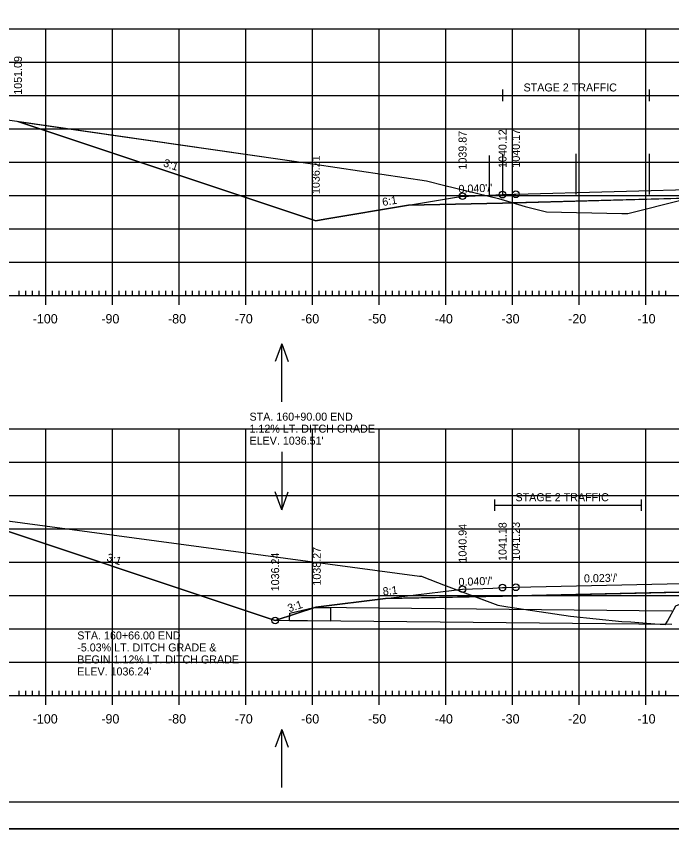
# Model space of a CAD drawing. Extents: x 1322838 to 1324533, y 339903 to 351025.
# Drawn here: x 1323599.3 to 1323697.6, y 345752.1 to 345873.9 of the extents above; entities that cross this region are included whole.
import ezdxf

# ---------------------------------------------------------------- set-up
doc = ezdxf.new("R2010")
doc.units = 0
for name, color, linetype in [('1', 7, 'Continuous'), ('R_Alt Surface', 7, 'Continuous'), ('R_Axis', 7, 'Continuous'), ('R_Axis Annot', 7, 'Continuous'), ('R_Border', 7, 'Continuous'), ('R_Drive', 7, 'Continuous'), ('R_Exist Surface', 7, 'Continuous'), ('R_Fin Surface', 7, 'Continuous'), ('R_Fin Surface Annot', 7, 'Continuous'), ('R_Grid', 7, 'Continuous'), ('R_No Plot', 7, 'Continuous'), ('R_Water', 7, 'Continuous'), ('R_Water Annot', 7, 'Continuous')]:
    doc.layers.add(name, color=color, linetype=linetype)

msp = doc.modelspace()

# ---------------------------------------------------------------- linework, layer by layer
at = {"layer": '1'}
msp.add_lwpolyline([(1323646.43, 345785.23), (1323646.41, 345783.23), (1323640.29, 345783.3), (1323640.3, 345784.42), (1323643.93, 345785.26)], close=True, dxfattribs=at)
at = {"layer": 'R_Alt Surface'}
for points in [[(1323658.11, 345845.61), (1323672.22, 345845.91), (1323710.1, 345846.95), (1323710.11, 345848.08), (1323732.11, 345848.69), (1323732.12, 345847.56), (1323735.22, 345847.65), (1323748.08, 345847.39)], [(1323654.65, 345786.62), (1323672.22, 345786.97), (1323710.03, 345787.84), (1323710.04, 345788.97), (1323732.03, 345789.47), (1323732.04, 345788.35), (1323735.22, 345788.42), (1323747.96, 345788.16)]]:
    msp.add_lwpolyline(points, dxfattribs=at)
at = {"layer": 'R_Axis'}
for p, q in [((1323599.72, 345832.08), (1323599.72, 345832.78)), ((1323600.72, 345832.08), (1323600.72, 345832.78)), ((1323601.72, 345832.08), (1323601.72, 345832.78)), ((1323602.72, 345832.08), (1323602.72, 345832.78)), ((1323603.72, 345830.68), (1323603.72, 345833.48)), ((1323604.72, 345832.08), (1323604.72, 345832.78)), ((1323605.72, 345832.08), (1323605.72, 345832.78)), ((1323606.72, 345832.08), (1323606.72, 345832.78)), ((1323607.72, 345832.08), (1323607.72, 345832.78)), ((1323608.72, 345832.08), (1323608.72, 345832.78)), ((1323609.72, 345832.08), (1323609.72, 345832.78)), ((1323610.72, 345832.08), (1323610.72, 345832.78)), ((1323611.72, 345832.08), (1323611.72, 345832.78)), ((1323612.72, 345832.08), (1323612.72, 345832.78)), ((1323613.72, 345830.68), (1323613.72, 345833.48)), ((1323614.72, 345832.08), (1323614.72, 345832.78)), ((1323615.72, 345832.08), (1323615.72, 345832.78)), ((1323616.72, 345832.08), (1323616.72, 345832.78)), ((1323617.72, 345832.08), (1323617.72, 345832.78)), ((1323618.72, 345832.08), (1323618.72, 345832.78)), ((1323619.72, 345832.08), (1323619.72, 345832.78)), ((1323620.72, 345832.08), (1323620.72, 345832.78)), ((1323621.72, 345832.08), (1323621.72, 345832.78)), ((1323622.72, 345832.08), (1323622.72, 345832.78)), ((1323623.72, 345830.68), (1323623.72, 345833.48)), ((1323624.72, 345832.08), (1323624.72, 345832.78)), ((1323625.72, 345832.08), (1323625.72, 345832.78)), ((1323626.72, 345832.08), (1323626.72, 345832.78)), ((1323627.72, 345832.08), (1323627.72, 345832.78)), ((1323628.72, 345832.08), (1323628.72, 345832.78)), ((1323629.72, 345832.08), (1323629.72, 345832.78)), ((1323630.72, 345832.08), (1323630.72, 345832.78)), ((1323631.72, 345832.08), (1323631.72, 345832.78)), ((1323632.72, 345832.08), (1323632.72, 345832.78)), ((1323633.72, 345830.68), (1323633.72, 345833.48)), ((1323634.72, 345832.08), (1323634.72, 345832.78)), ((1323635.72, 345832.08), (1323635.72, 345832.78)), ((1323636.72, 345832.08), (1323636.72, 345832.78)), ((1323637.72, 345832.08), (1323637.72, 345832.78)), ((1323638.72, 345832.08), (1323638.72, 345832.78)), ((1323639.72, 345832.08), (1323639.72, 345832.78)), ((1323640.72, 345832.08), (1323640.72, 345832.78)), ((1323641.72, 345832.08), (1323641.72, 345832.78)), ((1323642.72, 345832.08), (1323642.72, 345832.78)), ((1323643.72, 345830.68), (1323643.72, 345833.48)), ((1323644.72, 345832.08), (1323644.72, 345832.78)), ((1323645.72, 345832.08), (1323645.72, 345832.78)), ((1323646.72, 345832.08), (1323646.72, 345832.78)), ((1323647.72, 345832.08), (1323647.72, 345832.78)), ((1323648.72, 345832.08), (1323648.72, 345832.78)), ((1323649.72, 345832.08), (1323649.72, 345832.78)), ((1323650.72, 345832.08), (1323650.72, 345832.78)), ((1323651.72, 345832.08), (1323651.72, 345832.78)), ((1323652.72, 345832.08), (1323652.72, 345832.78)), ((1323653.72, 345830.68), (1323653.72, 345833.48)), ((1323654.72, 345832.08), (1323654.72, 345832.78)), ((1323655.72, 345832.08), (1323655.72, 345832.78)), ((1323656.72, 345832.08), (1323656.72, 345832.78)), ((1323657.72, 345832.08), (1323657.72, 345832.78)), ((1323658.72, 345832.08), (1323658.72, 345832.78)), ((1323659.72, 345832.08), (1323659.72, 345832.78)), ((1323660.72, 345832.08), (1323660.72, 345832.78)), ((1323661.72, 345832.08), (1323661.72, 345832.78)), ((1323662.72, 345832.08), (1323662.72, 345832.78)), ((1323663.72, 345830.68), (1323663.72, 345833.48)), ((1323664.72, 345832.08), (1323664.72, 345832.78)), ((1323665.72, 345832.08), (1323665.72, 345832.78)), ((1323666.72, 345832.08), (1323666.72, 345832.78)), ((1323667.72, 345832.08), (1323667.72, 345832.78)), ((1323668.72, 345832.08), (1323668.72, 345832.78)), ((1323669.72, 345832.08), (1323669.72, 345832.78)), ((1323670.72, 345832.08), (1323670.72, 345832.78)), ((1323671.72, 345832.08), (1323671.72, 345832.78)), ((1323672.72, 345832.08), (1323672.72, 345832.78)), ((1323673.72, 345830.68), (1323673.72, 345833.48)), ((1323674.72, 345832.08), (1323674.72, 345832.78)), ((1323675.72, 345832.08), (1323675.72, 345832.78)), ((1323676.72, 345832.08), (1323676.72, 345832.78)), ((1323677.72, 345832.08), (1323677.72, 345832.78)), ((1323678.72, 345832.08), (1323678.72, 345832.78)), ((1323679.72, 345832.08), (1323679.72, 345832.78)), ((1323680.72, 345832.08), (1323680.72, 345832.78)), ((1323681.72, 345832.08), (1323681.72, 345832.78)), ((1323682.72, 345832.08), (1323682.72, 345832.78)), ((1323683.72, 345830.68), (1323683.72, 345833.48)), ((1323684.72, 345832.08), (1323684.72, 345832.78)), ((1323685.72, 345832.08), (1323685.72, 345832.78)), ((1323686.72, 345832.08), (1323686.72, 345832.78)), ((1323687.72, 345832.08), (1323687.72, 345832.78)), ((1323688.72, 345832.08), (1323688.72, 345832.78)), ((1323689.72, 345832.08), (1323689.72, 345832.78)), ((1323690.72, 345832.08), (1323690.72, 345832.78)), ((1323691.72, 345832.08), (1323691.72, 345832.78)), ((1323692.72, 345832.08), (1323692.72, 345832.78)), ((1323693.72, 345830.68), (1323693.72, 345833.48)), ((1323694.72, 345832.08), (1323694.72, 345832.78)), ((1323695.72, 345832.08), (1323695.72, 345832.78)), ((1323696.72, 345832.08), (1323696.72, 345832.78)), ((1323563.72, 345832.08), (1323843.72, 345832.08)), ((1323599.72, 345772.08), (1323599.72, 345772.78)), ((1323600.72, 345772.08), (1323600.72, 345772.78)), ((1323601.72, 345772.08), (1323601.72, 345772.78)), ((1323602.72, 345772.08), (1323602.72, 345772.78)), ((1323603.72, 345770.68), (1323603.72, 345773.48)), ((1323604.72, 345772.08), (1323604.72, 345772.78)), ((1323605.72, 345772.08), (1323605.72, 345772.78)), ((1323606.72, 345772.08), (1323606.72, 345772.78)), ((1323607.72, 345772.08), (1323607.72, 345772.78)), ((1323608.72, 345772.08), (1323608.72, 345772.78)), ((1323609.72, 345772.08), (1323609.72, 345772.78)), ((1323610.72, 345772.08), (1323610.72, 345772.78)), ((1323611.72, 345772.08), (1323611.72, 345772.78)), ((1323612.72, 345772.08), (1323612.72, 345772.78)), ((1323613.72, 345770.68), (1323613.72, 345773.48)), ((1323614.72, 345772.08), (1323614.72, 345772.78)), ((1323615.72, 345772.08), (1323615.72, 345772.78)), ((1323616.72, 345772.08), (1323616.72, 345772.78)), ((1323617.72, 345772.08), (1323617.72, 345772.78)), ((1323618.72, 345772.08), (1323618.72, 345772.78)), ((1323619.72, 345772.08), (1323619.72, 345772.78)), ((1323620.72, 345772.08), (1323620.72, 345772.78)), ((1323621.72, 345772.08), (1323621.72, 345772.78)), ((1323622.72, 345772.08), (1323622.72, 345772.78)), ((1323623.72, 345770.68), (1323623.72, 345773.48)), ((1323624.72, 345772.08), (1323624.72, 345772.78)), ((1323625.72, 345772.08), (1323625.72, 345772.78)), ((1323626.72, 345772.08), (1323626.72, 345772.78)), ((1323627.72, 345772.08), (1323627.72, 345772.78)), ((1323628.72, 345772.08), (1323628.72, 345772.78)), ((1323629.72, 345772.08), (1323629.72, 345772.78)), ((1323630.72, 345772.08), (1323630.72, 345772.78)), ((1323631.72, 345772.08), (1323631.72, 345772.78)), ((1323632.72, 345772.08), (1323632.72, 345772.78)), ((1323633.72, 345770.68), (1323633.72, 345773.48)), ((1323634.72, 345772.08), (1323634.72, 345772.78)), ((1323635.72, 345772.08), (1323635.72, 345772.78)), ((1323636.72, 345772.08), (1323636.72, 345772.78)), ((1323637.72, 345772.08), (1323637.72, 345772.78)), ((1323638.72, 345772.08), (1323638.72, 345772.78)), ((1323639.72, 345772.08), (1323639.72, 345772.78)), ((1323640.72, 345772.08), (1323640.72, 345772.78)), ((1323641.72, 345772.08), (1323641.72, 345772.78)), ((1323642.72, 345772.08), (1323642.72, 345772.78)), ((1323643.72, 345770.68), (1323643.72, 345773.48)), ((1323644.72, 345772.08), (1323644.72, 345772.78)), ((1323645.72, 345772.08), (1323645.72, 345772.78)), ((1323646.72, 345772.08), (1323646.72, 345772.78)), ((1323647.72, 345772.08), (1323647.72, 345772.78)), ((1323648.72, 345772.08), (1323648.72, 345772.78)), ((1323649.72, 345772.08), (1323649.72, 345772.78)), ((1323650.72, 345772.08), (1323650.72, 345772.78)), ((1323651.72, 345772.08), (1323651.72, 345772.78)), ((1323652.72, 345772.08), (1323652.72, 345772.78)), ((1323653.72, 345770.68), (1323653.72, 345773.48)), ((1323654.72, 345772.08), (1323654.72, 345772.78)), ((1323655.72, 345772.08), (1323655.72, 345772.78)), ((1323656.72, 345772.08), (1323656.72, 345772.78)), ((1323657.72, 345772.08), (1323657.72, 345772.78)), ((1323658.72, 345772.08), (1323658.72, 345772.78)), ((1323659.72, 345772.08), (1323659.72, 345772.78)), ((1323660.72, 345772.08), (1323660.72, 345772.78)), ((1323661.72, 345772.08), (1323661.72, 345772.78)), ((1323662.72, 345772.08), (1323662.72, 345772.78)), ((1323663.72, 345770.68), (1323663.72, 345773.48)), ((1323664.72, 345772.08), (1323664.72, 345772.78)), ((1323665.72, 345772.08), (1323665.72, 345772.78)), ((1323666.72, 345772.08), (1323666.72, 345772.78)), ((1323667.72, 345772.08), (1323667.72, 345772.78)), ((1323668.72, 345772.08), (1323668.72, 345772.78)), ((1323669.72, 345772.08), (1323669.72, 345772.78)), ((1323670.72, 345772.08), (1323670.72, 345772.78)), ((1323671.72, 345772.08), (1323671.72, 345772.78)), ((1323672.72, 345772.08), (1323672.72, 345772.78)), ((1323673.72, 345770.68), (1323673.72, 345773.48)), ((1323674.72, 345772.08), (1323674.72, 345772.78)), ((1323675.72, 345772.08), (1323675.72, 345772.78)), ((1323676.72, 345772.08), (1323676.72, 345772.78)), ((1323677.72, 345772.08), (1323677.72, 345772.78)), ((1323678.72, 345772.08), (1323678.72, 345772.78)), ((1323679.72, 345772.08), (1323679.72, 345772.78)), ((1323680.72, 345772.08), (1323680.72, 345772.78)), ((1323681.72, 345772.08), (1323681.72, 345772.78)), ((1323682.72, 345772.08), (1323682.72, 345772.78)), ((1323683.72, 345770.68), (1323683.72, 345773.48)), ((1323684.72, 345772.08), (1323684.72, 345772.78)), ((1323685.72, 345772.08), (1323685.72, 345772.78)), ((1323686.72, 345772.08), (1323686.72, 345772.78)), ((1323687.72, 345772.08), (1323687.72, 345772.78)), ((1323688.72, 345772.08), (1323688.72, 345772.78)), ((1323689.72, 345772.08), (1323689.72, 345772.78)), ((1323690.72, 345772.08), (1323690.72, 345772.78)), ((1323691.72, 345772.08), (1323691.72, 345772.78)), ((1323692.72, 345772.08), (1323692.72, 345772.78)), ((1323693.72, 345770.68), (1323693.72, 345773.48)), ((1323694.72, 345772.08), (1323694.72, 345772.78)), ((1323695.72, 345772.08), (1323695.72, 345772.78)), ((1323696.72, 345772.08), (1323696.72, 345772.78)), ((1323563.72, 345772.08), (1323843.72, 345772.08))]:
    msp.add_line(p, q, dxfattribs=at)
at = {"layer": 'R_Axis Annot'}
for p, q in [((1323672.22, 345862.94), (1323672.22, 345861.23)), ((1323694.22, 345862.94), (1323694.22, 345861.23)), ((1323672.22, 345862.08), (1323694.22, 345862.08)), ((1323671.01, 345801.49), (1323671.01, 345799.78)), ((1323693.01, 345801.49), (1323693.01, 345799.78)), ((1323671.01, 345800.63), (1323693.01, 345800.63))]:
    msp.add_line(p, q, dxfattribs=at)
at = {"layer": 'R_Border'}
msp.add_line((1323861.9, 345756.08), (1323545.72, 345756.08), dxfattribs=at)
at = {"layer": 'R_Exist Surface'}
for points in [[(1323563.72, 345863.82), (1323572.81, 345862.34), (1323594.51, 345858.91), (1323644.06, 345851.75), (1323660.82, 345849.29), (1323663.56, 345848.56), (1323671.61, 345846.6), (1323675.63, 345845.41), (1323678.82, 345844.61), (1323690.12, 345844.38), (1323691.01, 345844.36), (1323691.58, 345844.51), (1323698.53, 345846.25)], [(1323563.72, 345803.99), (1323566.4, 345803.53), (1323588.01, 345799.93), (1323596.88, 345798.45), (1323659.75, 345790), (1323660.09, 345789.97), (1323660.43, 345789.83), (1323663.37, 345788.7), (1323671.5, 345785.64), (1323673.03, 345785.38), (1323682.43, 345783.99), (1323690.08, 345783.19), (1323691.46, 345783.11), (1323695.07, 345782.85), (1323696.66, 345782.74), (1323696.96, 345783.21), (1323698.22, 345785.54)]]:
    msp.add_lwpolyline(points, dxfattribs=at)
at = {"layer": 'R_Fin Surface'}
for points in [[(1323599.56, 345858.18), (1323644.21, 345843.29), (1323644.21, 345843.29), (1323645.56, 345843.52), (1323658.11, 345845.61), (1323666.22, 345846.96), (1323667.13, 345846.99), (1323672.22, 345847.2), (1323673.97, 345847.25), (1323674.22, 345847.25), (1323703.71, 345848.07), (1323703.72, 345848.07), (1323703.72, 345848.07), (1323733.22, 345848.88), (1323734.69, 345848.93), (1323735.22, 345848.94), (1323736.85, 345848.99), (1323741.22, 345849.11), (1323746.33, 345847.83), (1323748.08, 345847.39), (1323748.08, 345847.39), (1323763.22, 345843.61), (1323767.9, 345842.04), (1323768.87, 345841.72)], [(1323588.62, 345799.82), (1323588.8, 345799.8), (1323638.12, 345783.32), (1323638.12, 345783.32), (1323644.21, 345785.35), (1323644.22, 345785.35), (1323644.22, 345785.35), (1323654.65, 345786.62), (1323666.22, 345788.02), (1323666.22, 345788.02), (1323670.77, 345788.2), (1323672.21, 345788.26), (1323672.22, 345788.26), (1323672.68, 345788.27), (1323674.22, 345788.31), (1323703.7, 345788.99)]]:
    msp.add_lwpolyline(points, dxfattribs=at)
at = {"layer": 'R_Grid'}
for p, q in [((1323563.72, 345872.08), (1323843.72, 345872.08)), ((1323603.72, 345832.08), (1323603.72, 345872.08)), ((1323613.72, 345832.08), (1323613.72, 345872.08)), ((1323623.72, 345832.08), (1323623.72, 345872.08)), ((1323633.72, 345832.08), (1323633.72, 345872.08)), ((1323643.72, 345832.08), (1323643.72, 345872.08)), ((1323653.72, 345832.08), (1323653.72, 345872.08)), ((1323663.72, 345832.08), (1323663.72, 345872.08)), ((1323673.72, 345832.08), (1323673.72, 345872.08)), ((1323683.72, 345832.08), (1323683.72, 345872.08)), ((1323693.72, 345832.08), (1323693.72, 345872.08)), ((1323563.72, 345867.08), (1323843.72, 345867.08)), ((1323563.72, 345862.08), (1323843.72, 345862.08)), ((1323563.72, 345857.08), (1323843.72, 345857.08)), ((1323563.72, 345852.08), (1323843.72, 345852.08)), ((1323563.72, 345847.08), (1323843.72, 345847.08)), ((1323563.72, 345842.08), (1323843.72, 345842.08)), ((1323563.72, 345837.08), (1323843.72, 345837.08)), ((1323563.72, 345832.08), (1323843.72, 345832.08)), ((1323563.72, 345812.08), (1323843.72, 345812.08)), ((1323603.72, 345772.08), (1323603.72, 345812.08)), ((1323613.72, 345772.08), (1323613.72, 345812.08)), ((1323623.72, 345772.08), (1323623.72, 345812.08)), ((1323633.72, 345772.08), (1323633.72, 345812.08)), ((1323643.72, 345772.08), (1323643.72, 345812.08)), ((1323653.72, 345772.08), (1323653.72, 345812.08)), ((1323663.72, 345772.08), (1323663.72, 345812.08)), ((1323673.72, 345772.08), (1323673.72, 345812.08)), ((1323683.72, 345772.08), (1323683.72, 345812.08)), ((1323693.72, 345772.08), (1323693.72, 345812.08)), ((1323563.72, 345807.08), (1323843.72, 345807.08)), ((1323563.72, 345802.08), (1323843.72, 345802.08)), ((1323563.72, 345797.08), (1323843.72, 345797.08)), ((1323563.72, 345792.08), (1323843.72, 345792.08)), ((1323563.72, 345787.08), (1323843.72, 345787.08)), ((1323563.72, 345782.08), (1323843.72, 345782.08)), ((1323563.72, 345777.08), (1323843.72, 345777.08)), ((1323563.72, 345772.08), (1323843.72, 345772.08))]:
    msp.add_line(p, q, dxfattribs=at)
at = {"layer": 'R_No Plot'}
for p, q in [((1323670.22, 345853.08), (1323670.22, 345846.97)), ((1323672.22, 345853.34), (1323672.22, 345847.23)), ((1323683.22, 345853.34), (1323683.22, 345847.23)), ((1323694.22, 345853.34), (1323694.22, 345847.23)), ((1323533.31, 345752.1), (1323866.65, 345752.1))]:
    msp.add_line(p, q, dxfattribs=at)
for points in [[(1323533.31, 345965.44), (1323866.65, 345965.44), (1323866.65, 345752.1), (1323533.31, 345752.1)], [(1323779.64, 345961.54), (1323799.26, 345961.54), (1323799.26, 345951.66), (1323815.37, 345951.66), (1323838.57, 345951.66), (1323838.57, 345918.99), (1323861.77, 345918.99), (1323861.9, 345756.08), (1323545.72, 345756.08), (1323545.72, 345961.54)], [(1323599.56, 345858.18), (1323644.06, 345851.75), (1323660.82, 345849.29), (1323663.56, 345848.56), (1323671.61, 345846.6), (1323673.81, 345845.95), (1323672.22, 345845.91), (1323658.11, 345845.61), (1323645.56, 345843.52), (1323644.21, 345843.29), (1323644.21, 345843.29)], [(1323673.81, 345845.95), (1323675.63, 345845.41), (1323678.82, 345844.61), (1323690.12, 345844.38), (1323691.01, 345844.36), (1323691.58, 345844.51), (1323698.53, 345846.25), (1323702.07, 345846.73)], [(1323588.8, 345799.79), (1323596.88, 345798.45), (1323659.75, 345790), (1323660.09, 345789.97), (1323660.43, 345789.83), (1323663.37, 345788.7), (1323668.18, 345786.89), (1323654.65, 345786.62), (1323644.22, 345785.35), (1323644.22, 345785.35), (1323644.21, 345785.35), (1323638.12, 345783.32), (1323638.12, 345783.32)], [(1323668.18, 345786.89), (1323671.5, 345785.64), (1323673.03, 345785.38), (1323682.43, 345783.99), (1323690.08, 345783.19), (1323691.46, 345783.11), (1323695.07, 345782.85), (1323696.66, 345782.74), (1323696.96, 345783.21), (1323698.22, 345785.54), (1323700.51, 345786.48), (1323700.71, 345786.6), (1323704.78, 345787.69), (1323704.8, 345787.7), (1323704.8, 345787.7), (1323705.25, 345787.73), (1323672.22, 345786.97)]]:
    msp.add_lwpolyline(points, close=True, dxfattribs=at)
for centre in [(1323666.22, 345846.96), (1323672.22, 345847.2), (1323674.22, 345847.25), (1323666.22, 345788.02), (1323672.22, 345788.26), (1323674.22, 345788.31), (1323638.12, 345783.32)]:
    msp.add_circle(centre, 0.5, dxfattribs=at)
at = {"layer": 'R_Water'}
for p, q in [((1323697.59, 345784.72), (1323643.93, 345785.26)), ((1323697.59, 345782.72), (1323638.05, 345783.32))]:
    msp.add_line(p, q, dxfattribs=at)
at = {"layer": 'R_Water Annot'}
for p, q in [((1323639.11, 345824.83), (1323638.14, 345822.17)), ((1323639.11, 345816.14), (1323639.11, 345824.83)), ((1323639.11, 345824.83), (1323640.08, 345822.17)), ((1323639.11, 345808.64), (1323639.11, 345799.95)), ((1323639.11, 345799.95), (1323638.14, 345802.61)), ((1323639.11, 345799.95), (1323640.08, 345802.61)), ((1323639.11, 345766.97), (1323638.14, 345764.31)), ((1323639.11, 345758.28), (1323639.11, 345766.97)), ((1323639.11, 345766.97), (1323640.08, 345764.31))]:
    msp.add_line(p, q, dxfattribs=at)

# ---------------------------------------------------------------- texts
at = {"layer": 'R_Axis Annot'}
for s, height, p in [('STAGE 2 TRAFFIC', 1.2, (1323675.37, 345862.67)), ('-100', 1.4, (1323601.77, 345827.88)), ('-90', 1.4, (1323612.06, 345827.88)), ('-80', 1.4, (1323622.06, 345827.88)), ('-70', 1.4, (1323632.06, 345827.88)), ('-60', 1.4, (1323642.02, 345827.88)), ('-50', 1.4, (1323652.06, 345827.88)), ('-40', 1.4, (1323662.06, 345827.88)), ('-30', 1.4, (1323672.06, 345827.88)), ('-20', 1.4, (1323682.06, 345827.88)), ('-10', 1.4, (1323692.45, 345827.88)), ('STAGE 2 TRAFFIC', 1.2, (1323674.16, 345801.22)), ('-100', 1.4, (1323601.77, 345767.88)), ('-90', 1.4, (1323612.06, 345767.88)), ('-80', 1.4, (1323622.06, 345767.88)), ('-70', 1.4, (1323632.06, 345767.88)), ('-60', 1.4, (1323642.02, 345767.88)), ('-50', 1.4, (1323652.06, 345767.88)), ('-40', 1.4, (1323662.06, 345767.88)), ('-30', 1.4, (1323672.06, 345767.88)), ('-20', 1.4, (1323682.06, 345767.88)), ('-10', 1.4, (1323692.45, 345767.88))]:
    msp.add_text(s, height=height, dxfattribs=at).set_placement(p)
at = {"layer": 'R_Drive'}
for s, p in [('STA. 160+90.00 END', (1323634.28, 345813.3)), ('1.12% LT. DITCH GRADE', (1323634.28, 345811.5)), ("ELEV. 1036.51'", (1323634.28, 345809.7)), ('STA. 160+66.00 END ', (1323608.45, 345780.49)), ('-5.03% LT. DITCH GRADE &', (1323608.45, 345778.69)), ('BEGIN 1.12% LT. DITCH GRADE', (1323608.45, 345776.89)), ("ELEV. 1036.24'", (1323608.45, 345775.09))]:
    msp.add_text(s, height=1.2, dxfattribs=at).set_placement(p)
at = {"layer": 'R_Fin Surface Annot'}
for s, rotation, p in [('1051.09', 90, (1323600.16, 345862.18)), ('1040.12', 90, (1323672.82, 345851.2)), ('1040.17', 90, (1323674.82, 345851.25)), ('1039.87', 90, (1323666.82, 345850.96)), ('3:1', 341.5652, (1323621.26, 345851.47)), ('1036.21', 90, (1323644.81, 345847.29)), ("0.040'/'", 2.2908, (1323665.64, 345847.44)), ('6:1', 9.4603, (1323654.28, 345845.48)), ('1040.94', 90, (1323666.82, 345792.02)), ('1041.18', 90, (1323672.82, 345792.26)), ('1041.23', 90, (1323674.82, 345792.31)), ('3:1', 341.5652, (1323612.74, 345792.31)), ('1036.24', 90, (1323638.72, 345787.71)), ('1038.27', 90, (1323644.96, 345788.57)), ("0.040'/'", 2.2904, (1323665.64, 345788.5)), ("0.023'/'", 1.3185, (1323684.44, 345789.04)), ('8:1', 6.9147, (1323654.33, 345787.08)), ('3:1', 18.4349, (1323640.22, 345784.55))]:
    msp.add_text(s, height=1.2, rotation=rotation, dxfattribs=at).set_placement(p)

doc.saveas('drawing.dxf')
